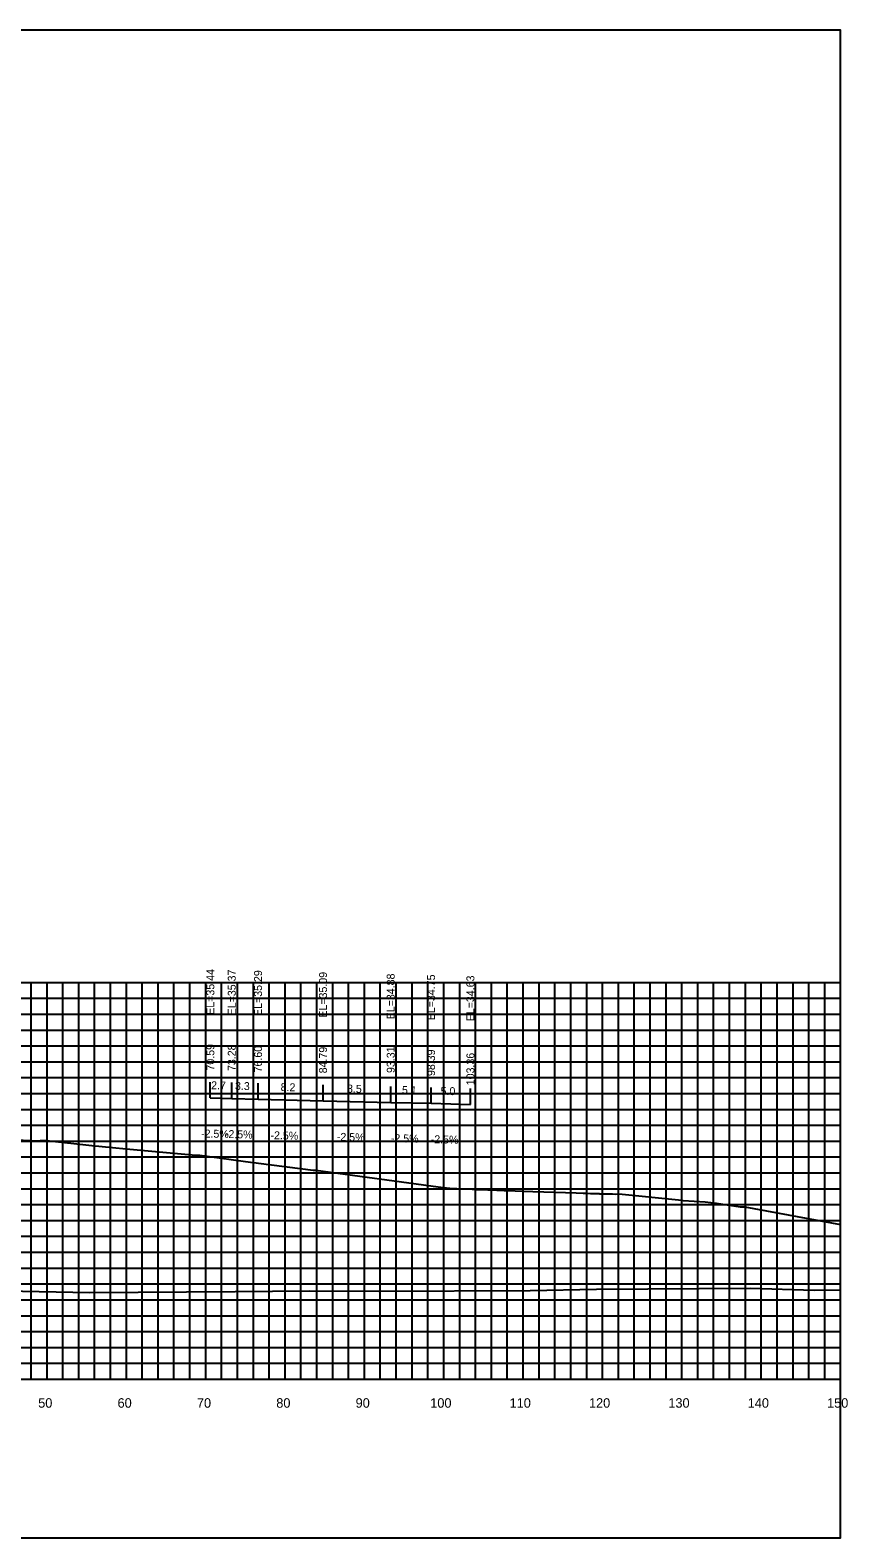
# Model space of a CAD drawing. Extents: x 1800880 to 1818864, y 245271 to 250560.
# Drawn here: x 1809268.2 to 1809371.3, y 249160.3 to 249350.3 of the extents above; entities that cross this region are included whole.
import ezdxf

# ---------------------------------------------------------------- set-up
doc = ezdxf.new("R2010")
doc.units = 0
for name, color, linetype in [('ANNO-TXT', 7, 'Continuous'), ('CL-CNST', 7, 'Continuous'), ('DESIGN - DRAINAGE - Bridges', 7, 'Continuous'), ('Level 37', 7, 'Continuous'), ('Level 46', 7, 'Continuous'), ('Level 62', 7, 'Continuous'), ('SHT-BDR', 7, 'Continuous')]:
    doc.layers.add(name, color=color, linetype=linetype)

msp = doc.modelspace()

# ---------------------------------------------------------------- linework, layer by layer
at = {"layer": 'CL-CNST'}
msp.add_lwpolyline([(1809266.53, 249210.44), (1809269.09, 249210.35), (1809269.49, 249210.36), (1809270.27, 249210.38), (1809270.29, 249210.38), (1809276, 249209.74), (1809278.63, 249209.49), (1809280.34, 249209.33), (1809289.13, 249208.51), (1809289.52, 249208.51), (1809289.63, 249208.51), (1809296.29, 249207.61), (1809296.72, 249207.55), (1809296.99, 249207.52), (1809303.91, 249206.62), (1809304.25, 249206.63), (1809319.65, 249204.54), (1809321.09, 249204.35), (1809321.15, 249204.34), (1809321.5, 249204.33), (1809321.68, 249204.32), (1809321.8, 249204.31), (1809321.88, 249204.31), (1809321.93, 249204.31), (1809321.98, 249204.31), (1809322.01, 249204.3), (1809322.04, 249204.3), (1809322.06, 249204.3), (1809322.08, 249204.3), (1809322.26, 249204.26), (1809322.41, 249204.29), (1809322.63, 249204.28), (1809323.93, 249204.23), (1809324.03, 249204.23), (1809324.13, 249204.23), (1809324.25, 249204.22), (1809324.38, 249204.22), (1809324.54, 249204.21), (1809324.72, 249204.2), (1809324.93, 249204.2), (1809325.19, 249204.19), (1809325.5, 249204.18), (1809325.89, 249204.16), (1809326.39, 249204.15), (1809327.05, 249204.12), (1809327.97, 249204.09), (1809329.33, 249204.04), (1809331.58, 249203.96), (1809335.68, 249203.81), (1809337.05, 249203.77), (1809337.9, 249203.74), (1809338.46, 249203.72), (1809338.85, 249203.71), (1809339.14, 249203.7), (1809339.37, 249203.7), (1809339.55, 249203.69), (1809339.69, 249203.68), (1809339.81, 249203.68), (1809339.92, 249203.68), (1809340, 249203.67), (1809340.08, 249203.67), (1809340.15, 249203.67), (1809340.2, 249203.67), (1809340.25, 249203.67), (1809341.17, 249203.64), (1809341.29, 249203.67), (1809341.3, 249203.67), (1809341.63, 249203.65), (1809341.96, 249203.63), (1809342.36, 249203.65), (1809342.41, 249203.65), (1809349.92, 249202.88), (1809350.5, 249202.83), (1809353.31, 249202.65), (1809354.73, 249202.47), (1809357.7, 249202.01), (1809358.16, 249202), (1809358.27, 249202), (1809370.36, 249199.79)], dxfattribs=at)
at = {"layer": 'DESIGN - DRAINAGE - Bridges'}
for p, q in [((1809370.36, 249180.3), (1809370.36, 249230.3)), ((1809370.42, 249230.3), (1809370.36, 249230.3)), ((1809370.42, 249220.3), (1809370.36, 249220.3)), ((1809370.42, 249210.3), (1809370.36, 249210.3)), ((1809370.42, 249200.3), (1809370.36, 249200.3)), ((1809370.42, 249190.3), (1809370.36, 249190.3)), ((1809070.36, 249180.3), (1809370.36, 249180.3)), ((1809270.36, 249180.24), (1809270.36, 249180.3)), ((1809280.36, 249180.24), (1809280.36, 249180.3)), ((1809290.36, 249180.24), (1809290.36, 249180.3)), ((1809300.36, 249180.24), (1809300.36, 249180.3)), ((1809310.36, 249180.24), (1809310.36, 249180.3)), ((1809320.36, 249180.24), (1809320.36, 249180.3)), ((1809330.36, 249180.24), (1809330.36, 249180.3)), ((1809340.36, 249180.24), (1809340.36, 249180.3)), ((1809350.36, 249180.24), (1809350.36, 249180.3)), ((1809360.36, 249180.24), (1809360.36, 249180.3)), ((1809370.36, 249180.24), (1809370.36, 249180.3)), ((1809370.42, 249180.3), (1809370.36, 249180.3))]:
    msp.add_line(p, q, dxfattribs=at)
at = {"layer": 'Level 37'}
for p, q in [((1809290.94, 249215.74), (1809290.94, 249217.74)), ((1809293.64, 249215.68), (1809293.64, 249217.68)), ((1809296.95, 249215.59), (1809296.95, 249217.59)), ((1809305.14, 249215.39), (1809305.14, 249217.39)), ((1809313.67, 249215.18), (1809313.67, 249217.18)), ((1809318.75, 249215.06), (1809318.75, 249217.06)), ((1809323.71, 249214.93), (1809323.71, 249216.93))]:
    msp.add_line(p, q, dxfattribs=at)
msp.add_lwpolyline([(1809070.36, 249160.3), (1809370.36, 249160.3), (1809370.36, 249350.3), (1809070.36, 249350.3)], close=True, dxfattribs=at)
at = {"layer": 'Level 46'}
for p, q in [((1809070.36, 249230.3), (1809370.36, 249230.3)), ((1809268.36, 249180.3), (1809268.36, 249230.3)), ((1809270.36, 249180.3), (1809270.36, 249230.3)), ((1809272.36, 249180.3), (1809272.36, 249230.3)), ((1809274.36, 249180.3), (1809274.36, 249230.3)), ((1809276.36, 249180.3), (1809276.36, 249230.3)), ((1809278.36, 249180.3), (1809278.36, 249230.3)), ((1809280.36, 249180.3), (1809280.36, 249230.3)), ((1809282.36, 249180.3), (1809282.36, 249230.3)), ((1809284.36, 249180.3), (1809284.36, 249230.3)), ((1809286.36, 249180.3), (1809286.36, 249230.3)), ((1809288.36, 249180.3), (1809288.36, 249230.3)), ((1809290.36, 249180.3), (1809290.36, 249230.3)), ((1809292.36, 249180.3), (1809292.36, 249230.3)), ((1809294.36, 249180.3), (1809294.36, 249230.3)), ((1809296.36, 249180.3), (1809296.36, 249230.3)), ((1809298.36, 249180.3), (1809298.36, 249230.3)), ((1809300.36, 249180.3), (1809300.36, 249230.3)), ((1809302.36, 249180.3), (1809302.36, 249230.3)), ((1809304.36, 249180.3), (1809304.36, 249230.3)), ((1809306.36, 249180.3), (1809306.36, 249230.3)), ((1809308.36, 249180.3), (1809308.36, 249230.3)), ((1809310.36, 249180.3), (1809310.36, 249230.3)), ((1809312.36, 249180.3), (1809312.36, 249230.3)), ((1809314.36, 249180.3), (1809314.36, 249230.3)), ((1809316.36, 249180.3), (1809316.36, 249230.3)), ((1809318.36, 249180.3), (1809318.36, 249230.3)), ((1809320.36, 249180.3), (1809320.36, 249230.3)), ((1809322.36, 249180.3), (1809322.36, 249230.3)), ((1809324.36, 249180.3), (1809324.36, 249230.3)), ((1809326.36, 249180.3), (1809326.36, 249230.3)), ((1809328.36, 249180.3), (1809328.36, 249230.3)), ((1809330.36, 249180.3), (1809330.36, 249230.3)), ((1809332.36, 249180.3), (1809332.36, 249230.3)), ((1809334.36, 249180.3), (1809334.36, 249230.3)), ((1809336.36, 249180.3), (1809336.36, 249230.3)), ((1809338.36, 249180.3), (1809338.36, 249230.3)), ((1809340.36, 249180.3), (1809340.36, 249230.3)), ((1809342.36, 249180.3), (1809342.36, 249230.3)), ((1809344.36, 249180.3), (1809344.36, 249230.3)), ((1809346.36, 249180.3), (1809346.36, 249230.3)), ((1809348.36, 249180.3), (1809348.36, 249230.3)), ((1809350.36, 249180.3), (1809350.36, 249230.3)), ((1809352.36, 249180.3), (1809352.36, 249230.3)), ((1809354.36, 249180.3), (1809354.36, 249230.3)), ((1809356.36, 249180.3), (1809356.36, 249230.3)), ((1809358.36, 249180.3), (1809358.36, 249230.3)), ((1809360.36, 249180.3), (1809360.36, 249230.3)), ((1809362.36, 249180.3), (1809362.36, 249230.3)), ((1809364.36, 249180.3), (1809364.36, 249230.3)), ((1809366.36, 249180.3), (1809366.36, 249230.3)), ((1809368.36, 249180.3), (1809368.36, 249230.3)), ((1809370.36, 249180.3), (1809370.36, 249230.3)), ((1809070.36, 249228.3), (1809370.36, 249228.3)), ((1809070.36, 249226.3), (1809370.36, 249226.3)), ((1809070.36, 249224.3), (1809370.36, 249224.3)), ((1809070.36, 249222.3), (1809370.36, 249222.3)), ((1809070.36, 249220.3), (1809370.36, 249220.3)), ((1809070.36, 249218.3), (1809370.36, 249218.3)), ((1809070.36, 249216.3), (1809370.36, 249216.3)), ((1809070.36, 249214.3), (1809370.36, 249214.3)), ((1809070.36, 249212.3), (1809370.36, 249212.3)), ((1809070.36, 249210.3), (1809370.36, 249210.3)), ((1809070.36, 249208.3), (1809370.36, 249208.3)), ((1809070.36, 249206.3), (1809370.36, 249206.3)), ((1809070.36, 249204.3), (1809370.36, 249204.3)), ((1809070.36, 249202.3), (1809370.36, 249202.3)), ((1809070.36, 249200.3), (1809370.36, 249200.3)), ((1809070.36, 249198.3), (1809370.36, 249198.3)), ((1809070.36, 249196.3), (1809370.36, 249196.3)), ((1809070.36, 249194.3), (1809370.36, 249194.3)), ((1809070.36, 249192.3), (1809370.36, 249192.3)), ((1809070.36, 249190.3), (1809370.36, 249190.3)), ((1809070.36, 249188.3), (1809370.36, 249188.3)), ((1809070.36, 249186.3), (1809370.36, 249186.3)), ((1809070.36, 249184.3), (1809370.36, 249184.3)), ((1809070.36, 249182.3), (1809370.36, 249182.3)), ((1809070.36, 249180.3), (1809370.36, 249180.3))]:
    msp.add_line(p, q, dxfattribs=at)
at = {"layer": 'Level 62'}
for points in [[(1809290.94, 249215.74), (1809293.64, 249215.68), (1809296.95, 249215.59), (1809305.14, 249215.39), (1809313.67, 249215.18), (1809318.75, 249215.06), (1809323.71, 249214.93)], [(1809070.36, 249191.88), (1809081.43, 249191.8), (1809086.23, 249191.78), (1809109.19, 249191.57), (1809117.14, 249191.56), (1809136.94, 249191.43), (1809147.44, 249191.43), (1809164.7, 249191.31), (1809177.31, 249191.33), (1809192.45, 249191.22), (1809206.84, 249191.27), (1809220.21, 249191.23), (1809236.11, 249191.3), (1809247.97, 249191.31), (1809265.17, 249191.41), (1809275.72, 249191.22), (1809294.07, 249191.33), (1809303.48, 249191.43), (1809312.15, 249191.38), (1809331.23, 249191.49), (1809339.6, 249191.64), (1809358.99, 249191.75), (1809367.03, 249191.53), (1809370.36, 249191.55)]]:
    msp.add_lwpolyline(points, dxfattribs=at)

# ---------------------------------------------------------------- texts
for s, p in [('50', (1809269.25, 249176.7)), ('60', (1809279.25, 249176.7)), ('70', (1809289.25, 249176.7)), ('80', (1809299.25, 249176.7)), ('90', (1809309.25, 249176.7)), ('100', (1809318.65, 249176.7)), ('110', (1809328.65, 249176.7)), ('120', (1809338.65, 249176.7)), ('130', (1809348.65, 249176.7)), ('140', (1809358.65, 249176.7)), ('150', (1809368.65, 249176.7))]:
    msp.add_text(s, height=1.2).set_placement(p)
at = {"layer": 'ANNO-TXT'}
for s, p in [('2.7', (1809291.03, 249216.84)), ('3.3', (1809294.04, 249216.77)), ('8.2', (1809299.79, 249216.62)), ('8.5', (1809308.15, 249216.42)), ('5.1', (1809315.08, 249216.25)), ('5.0', (1809319.94, 249216.13)), ('-2.5%', (1809289.76, 249210.77)), ('-2.5%', (1809292.76, 249210.7)), ('-2.5%', (1809298.51, 249210.55)), ('-2.5%', (1809306.87, 249210.35)), ('-2.5%', (1809313.68, 249210.18)), ('-2.5%', (1809318.7, 249210.05))]:
    msp.add_text(s, height=1, rotation=358.5827, dxfattribs=at).set_placement(p)
at = {"layer": 'SHT-BDR'}
for s, p in [('EL=35.44', (1809291.44, 249226.22)), ('EL=35.37', (1809294.14, 249226.15)), ('EL=35.29', (1809297.45, 249226.07)), ('EL=35.09', (1809305.64, 249225.86)), ('EL=34.88', (1809314.17, 249225.65)), ('EL=34.75', (1809319.25, 249225.53)), ('EL=34.63', (1809324.21, 249225.4)), ('70.59', (1809291.44, 249219.19)), ('73.28', (1809294.14, 249219.13)), ('76.60', (1809297.45, 249218.96)), ('84.79', (1809305.64, 249218.84)), ('93.31', (1809314.17, 249218.88)), ('98.39', (1809319.25, 249218.5)), ('103.36', (1809324.21, 249217.34))]:
    msp.add_text(s, height=1, rotation=90, dxfattribs=at).set_placement(p)

doc.saveas('drawing.dxf')
